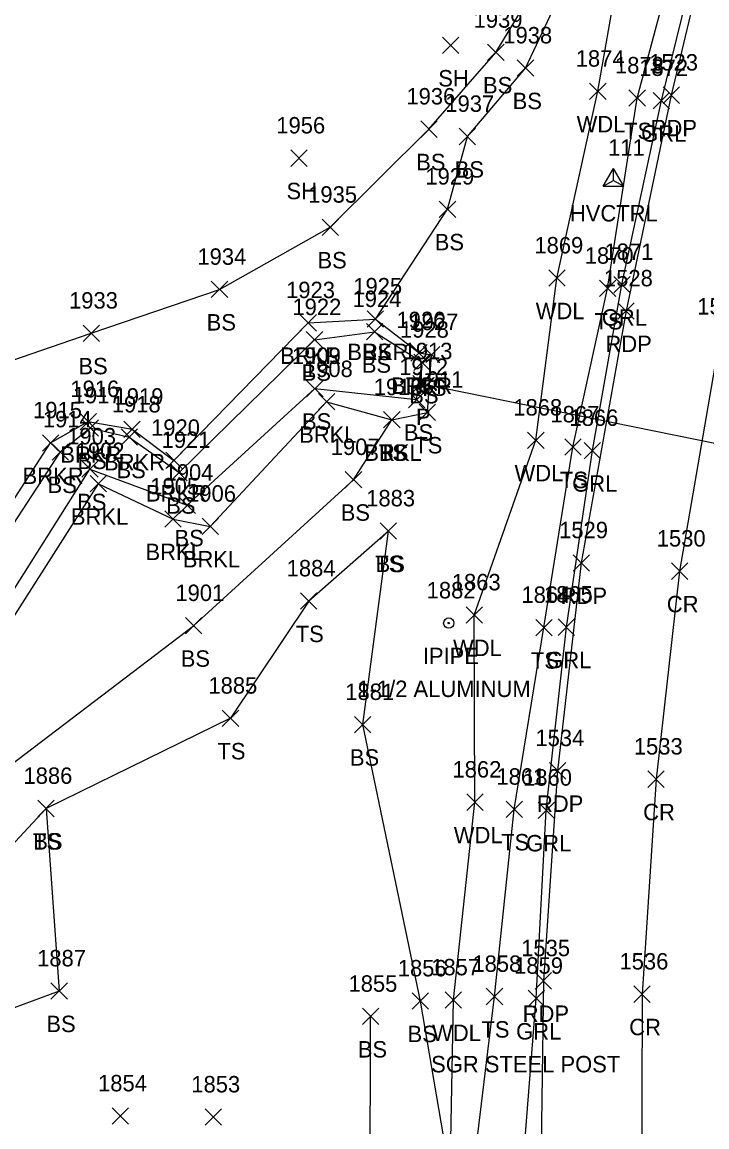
# Model space of a CAD drawing. Extents: x 1885914 to 1887218, y 756253 to 760620.
# Drawn here: x 1886356.8 to 1886440.2, y 759652.9 to 759787.4 of the extents above; entities that cross this region are included whole.
import ezdxf

# ---------------------------------------------------------------- set-up
doc = ezdxf.new("R2010")
doc.units = 0
for name, color, linetype in [('C_A', 7, 'Continuous'), ('C_I', 7, 'Continuous'), ('CPSM', 7, 'Continuous'), ('D_A', 7, 'Continuous'), ('D_I', 7, 'Continuous'), ('D_TIC', 7, 'Continuous'), ('DCP', 7, 'Continuous'), ('L_A', 7, 'Continuous'), ('L_I', 7, 'Continuous'), ('L_TIC', 7, 'Continuous'), ('LAWA', 7, 'Continuous'), ('LAWE', 7, 'Continuous'), ('LELB', 7, 'Continuous'), ('M_A', 7, 'Continuous'), ('M_C', 7, 'Continuous'), ('M_I', 7, 'Continuous'), ('MPIP', 7, 'Continuous'), ('P_A', 7, 'Continuous'), ('P_I', 7, 'Continuous'), ('P_TIC', 7, 'Continuous'), ('PET', 7, 'Continuous'), ('PRC', 7, 'Continuous'), ('R_A', 7, 'Continuous'), ('R_C', 7, 'Continuous'), ('R_I', 7, 'Continuous'), ('R_TIC', 7, 'Continuous'), ('RGR', 7, 'Continuous')]:
    doc.layers.add(name, color=color, linetype=linetype)

msp = doc.modelspace()

# ---------------------------------------------------------------- linework, layer by layer
at = {"layer": 'CPSM'}
for p, q in [((1886427.59, 759767.4), (1886428.84, 759769.57)), ((1886430.09, 759767.4), (1886428.84, 759769.57)), ((1886428.84, 759768.12), (1886428.84, 759769.57)), ((1886427.59, 759767.4), (1886428.84, 759768.12)), ((1886428.84, 759768.12), (1886428.84, 759768.12)), ((1886428.84, 759768.12), (1886430.09, 759767.4)), ((1886427.59, 759767.4), (1886430.09, 759767.4))]:
    msp.add_line(p, q, dxfattribs=at)
at = {"layer": 'D_TIC'}
for points in [[(1886404.41, 759742.36), (1886406.41, 759744.36)], [(1886406.41, 759742.36), (1886404.41, 759744.36)]]:
    msp.add_lwpolyline(points, dxfattribs=at)
at = {"layer": 'DCP'}
msp.add_lwpolyline([(1886482.74, 759727.67), (1886405.41, 759743.36)], dxfattribs=at)
at = {"layer": 'L_TIC'}
for points in [[(1886408.01, 759783.55), (1886410.01, 759785.55)], [(1886410.01, 759783.55), (1886408.01, 759785.55)], [(1886413.51, 759782.7), (1886415.51, 759784.7)], [(1886415.51, 759782.7), (1886413.51, 759784.7)], [(1886417.12, 759780.79), (1886419.12, 759782.79)], [(1886419.12, 759780.79), (1886417.12, 759782.79)], [(1886425.93, 759777.96), (1886427.93, 759779.96)], [(1886427.93, 759777.96), (1886425.93, 759779.96)], [(1886430.72, 759777.14), (1886432.72, 759779.14)], [(1886432.72, 759777.14), (1886430.72, 759779.14)], [(1886405.37, 759773.36), (1886407.37, 759775.36)], [(1886407.37, 759773.36), (1886405.37, 759775.36)], [(1886410.05, 759772.46), (1886412.05, 759774.46)], [(1886412.05, 759772.46), (1886410.05, 759774.46)], [(1886389.53, 759769.83), (1886391.53, 759771.83)], [(1886391.53, 759769.83), (1886389.53, 759771.83)], [(1886407.63, 759763.61), (1886409.63, 759765.61)], [(1886409.63, 759763.61), (1886407.63, 759765.61)], [(1886393.35, 759761.41), (1886395.35, 759763.41)], [(1886395.35, 759761.41), (1886393.35, 759763.41)], [(1886420.95, 759755.23), (1886422.95, 759757.23)], [(1886422.95, 759755.23), (1886420.95, 759757.23)], [(1886379.86, 759753.85), (1886381.86, 759755.85)], [(1886381.86, 759753.85), (1886379.86, 759755.85)], [(1886427.12, 759753.98), (1886429.12, 759755.98)], [(1886429.12, 759753.98), (1886427.12, 759755.98)], [(1886390.66, 759749.79), (1886392.66, 759751.79)], [(1886392.66, 759749.79), (1886390.66, 759751.79)], [(1886398.84, 759750.25), (1886400.84, 759752.25)], [(1886400.84, 759750.25), (1886398.84, 759752.25)], [(1886398.84, 759750.25), (1886400.84, 759752.25)], [(1886400.84, 759750.25), (1886398.84, 759752.25)], [(1886364.24, 759748.52), (1886366.24, 759750.52)], [(1886366.24, 759748.52), (1886364.24, 759750.52)], [(1886398.75, 759748.71), (1886400.75, 759750.71)], [(1886400.75, 759748.71), (1886398.75, 759750.71)], [(1886391.43, 759747.73), (1886393.43, 759749.73)], [(1886393.43, 759747.73), (1886391.43, 759749.73)], [(1886404.16, 759746.14), (1886406.16, 759748.14)], [(1886406.16, 759746.14), (1886404.16, 759748.14)], [(1886404.16, 759746.14), (1886406.16, 759748.14)], [(1886406.16, 759746.14), (1886404.16, 759748.14)], [(1886405.68, 759745.9), (1886407.68, 759747.9)], [(1886407.68, 759745.9), (1886405.68, 759747.9)], [(1886405.68, 759745.9), (1886407.68, 759747.9)], [(1886407.68, 759745.9), (1886405.68, 759747.9)], [(1886404.53, 759744.98), (1886406.53, 759746.98)], [(1886406.53, 759744.98), (1886404.53, 759746.98)], [(1886404.53, 759744.98), (1886406.53, 759746.98)], [(1886406.53, 759744.98), (1886404.53, 759746.98)], [(1886391.47, 759741.78), (1886393.47, 759743.78)], [(1886393.47, 759741.78), (1886391.47, 759743.78)], [(1886392.91, 759740.19), (1886394.91, 759742.19)], [(1886394.91, 759740.19), (1886392.91, 759742.19)], [(1886403.87, 759740.44), (1886405.87, 759742.44)], [(1886405.87, 759740.44), (1886403.87, 759742.44)], [(1886405.17, 759738.89), (1886407.17, 759740.89)], [(1886407.17, 759738.89), (1886405.17, 759740.89)], [(1886363.88, 759737.76), (1886365.88, 759739.76)], [(1886365.88, 759737.76), (1886363.88, 759739.76)], [(1886400.85, 759737.99), (1886402.85, 759739.99)], [(1886402.85, 759737.99), (1886400.85, 759739.99)], [(1886400.85, 759737.99), (1886402.85, 759739.99)], [(1886402.85, 759737.99), (1886400.85, 759739.99)], [(1886400.85, 759737.99), (1886402.85, 759739.99)], [(1886402.85, 759737.99), (1886400.85, 759739.99)], [(1886364.13, 759736.99), (1886366.13, 759738.99)], [(1886366.13, 759736.99), (1886364.13, 759738.99)], [(1886369.21, 759736.83), (1886371.21, 759738.83)], [(1886371.21, 759736.83), (1886369.21, 759738.83)], [(1886359.29, 759735.17), (1886361.29, 759737.17)], [(1886361.29, 759735.17), (1886359.29, 759737.17)], [(1886368.88, 759735.88), (1886370.88, 759737.88)], [(1886370.88, 759735.88), (1886368.88, 759737.88)], [(1886418.38, 759735.5), (1886420.38, 759737.5)], [(1886420.38, 759735.5), (1886418.38, 759737.5)], [(1886360.48, 759734.07), (1886362.48, 759736.07)], [(1886362.48, 759734.07), (1886360.48, 759736.07)], [(1886422.9, 759734.67), (1886424.9, 759736.67)], [(1886424.9, 759734.67), (1886422.9, 759736.67)], [(1886374.31, 759733.04), (1886376.31, 759735.04)], [(1886376.31, 759733.04), (1886374.31, 759735.04)], [(1886364.08, 759731.99), (1886366.08, 759733.99)], [(1886366.08, 759731.99), (1886364.08, 759733.99)], [(1886374.93, 759731.56), (1886376.93, 759733.56)], [(1886376.93, 759731.56), (1886374.93, 759733.56)], [(1886365.11, 759730.21), (1886367.11, 759732.21)], [(1886367.11, 759730.21), (1886365.11, 759732.21)], [(1886396.18, 759730.7), (1886398.18, 759732.7)], [(1886398.18, 759730.7), (1886396.18, 759732.7)], [(1886375.94, 759727.59), (1886377.94, 759729.59)], [(1886377.94, 759727.59), (1886375.94, 759729.59)], [(1886374.2, 759725.91), (1886376.2, 759727.91)], [(1886376.2, 759725.91), (1886374.2, 759727.91)], [(1886378.74, 759725.02), (1886380.74, 759727.02)], [(1886380.74, 759725.02), (1886378.74, 759727.02)], [(1886400.43, 759724.45), (1886402.43, 759726.45)], [(1886402.43, 759724.45), (1886400.43, 759726.45)], [(1886400.43, 759724.45), (1886402.43, 759726.45)], [(1886402.43, 759724.45), (1886400.43, 759726.45)], [(1886390.73, 759715.93), (1886392.73, 759717.93)], [(1886392.73, 759715.93), (1886390.73, 759717.93)], [(1886410.89, 759714.23), (1886412.89, 759716.23)], [(1886412.89, 759714.23), (1886410.89, 759716.23)], [(1886376.7, 759712.93), (1886378.7, 759714.93)], [(1886378.7, 759712.93), (1886376.7, 759714.93)], [(1886419.37, 759712.7), (1886421.37, 759714.7)], [(1886421.37, 759712.7), (1886419.37, 759714.7)], [(1886381.2, 759701.66), (1886383.2, 759703.66)], [(1886383.2, 759701.66), (1886381.2, 759703.66)], [(1886397.3, 759700.89), (1886399.3, 759702.89)], [(1886399.3, 759700.89), (1886397.3, 759702.89)], [(1886358.74, 759690.68), (1886360.74, 759692.68)], [(1886360.74, 759690.68), (1886358.74, 759692.68)], [(1886358.74, 759690.68), (1886360.74, 759692.68)], [(1886360.74, 759690.68), (1886358.74, 759692.68)], [(1886410.97, 759691.45), (1886412.97, 759693.45)], [(1886412.97, 759691.45), (1886410.97, 759693.45)], [(1886415.75, 759690.58), (1886417.75, 759692.58)], [(1886417.75, 759690.58), (1886415.75, 759692.58)], [(1886360.34, 759668.47), (1886362.34, 759670.47)], [(1886362.34, 759668.47), (1886360.34, 759670.47)], [(1886413.35, 759667.8), (1886415.35, 759669.8)], [(1886415.35, 759667.8), (1886413.35, 759669.8)], [(1886404.32, 759667.25), (1886406.32, 759669.25)], [(1886406.32, 759667.25), (1886404.32, 759669.25)], [(1886408.34, 759667.38), (1886410.34, 759669.38)], [(1886410.34, 759667.38), (1886408.34, 759669.38)], [(1886398.26, 759665.38), (1886400.26, 759667.38)], [(1886400.26, 759665.38), (1886398.26, 759667.38)], [(1886367.77, 759653.26), (1886369.77, 759655.26)], [(1886369.77, 759653.26), (1886367.77, 759655.26)], [(1886379.12, 759653.13), (1886381.12, 759655.13)], [(1886381.12, 759653.13), (1886379.12, 759655.13)]]:
    msp.add_lwpolyline(points, dxfattribs=at)
at = {"layer": 'LAWA'}
msp.add_lwpolyline([(1886420.25, 759558.57), (1886411.95, 759586.16), (1886411.02, 759591.73), (1886408.64, 759606.82), (1886405.28, 759619.96), (1886408.97, 759647.11), (1886409.34, 759668.38), (1886411.97, 759692.45), (1886411.89, 759715.23), (1886419.38, 759736.5), (1886421.95, 759756.23), (1886426.93, 759778.96), (1886430, 759796.54), (1886430.97, 759806.71), (1886430.75, 759808.98), (1886434.23, 759819.8), (1886435.82, 759833.71), (1886420.59, 759830.9), (1886400.43, 759842), (1886371.48, 759869.99)], dxfattribs=at)
at = {"layer": 'LAWE'}
for points in [[(1886317, 759683.03), (1886341.18, 759706.68), (1886360.29, 759736.17), (1886364.88, 759738.76), (1886370.21, 759737.83), (1886375.31, 759734.04), (1886391.66, 759750.79), (1886399.84, 759751.25), (1886405.16, 759747.14)], [(1886319.97, 759675.42), (1886346.73, 759700.79), (1886366.11, 759731.21), (1886375.2, 759726.91), (1886379.74, 759726.02), (1886393.91, 759741.19), (1886401.85, 759738.99)]]:
    msp.add_lwpolyline(points, dxfattribs=at)
at = {"layer": 'LELB'}
for points in [[(1886482.43, 759330.53), (1886473.8, 759362.16), (1886466.41, 759391.35), (1886456.38, 759428.48), (1886448.84, 759459.02), (1886441.76, 759486.12), (1886435.76, 759515.56), (1886431.42, 759535.05), (1886426.06, 759559.46), (1886421.11, 759588.4), (1886418.79, 759606.26), (1886412.24, 759623.91), (1886411.78, 759647.7), (1886414.35, 759668.8), (1886416.75, 759691.58), (1886420.37, 759713.7), (1886423.9, 759735.67), (1886428.12, 759754.98), (1886431.72, 759778.14), (1886436.25, 759795.18), (1886439.73, 759830.38)], [(1886307, 759709.14), (1886318.52, 759725.02), (1886338.68, 759740.39), (1886365.24, 759749.52), (1886380.86, 759754.85), (1886394.35, 759762.41), (1886406.37, 759774.36), (1886414.51, 759783.7), (1886422.61, 759797.12), (1886430.75, 759808.98)], [(1886399.84, 759751.25), (1886408.63, 759764.61), (1886411.05, 759773.46), (1886418.12, 759781.79), (1886424.84, 759796), (1886430.97, 759806.71)], [(1886317.21, 759681.25), (1886341.81, 759704.94), (1886361.48, 759735.07), (1886365.13, 759737.99), (1886369.88, 759736.88), (1886375.93, 759732.56), (1886392.43, 759748.73), (1886399.75, 759749.71), (1886405.53, 759745.98)], [(1886401.85, 759738.99), (1886406.17, 759739.89), (1886406.68, 759746.9)], [(1886405.16, 759747.14), (1886406.68, 759746.9)], [(1886319.13, 759676.73), (1886345.61, 759702.22), (1886365.08, 759732.99), (1886376.94, 759728.59), (1886392.47, 759742.78), (1886404.87, 759741.44), (1886405.53, 759745.98)], [(1886304.72, 759654.88), (1886325.87, 759667.69), (1886353.55, 759695.57), (1886377.7, 759713.93), (1886397.18, 759731.7), (1886401.85, 759738.99)], [(1886401.43, 759725.45), (1886391.73, 759716.93), (1886382.2, 759702.66), (1886359.74, 759691.68), (1886327.3, 759656.86)], [(1886479.66, 759329.52), (1886471.03, 759361.21), (1886461.96, 759390.83), (1886454.24, 759427.83), (1886447.27, 759458.84), (1886440.35, 759485.71), (1886434.88, 759515.3), (1886430.89, 759534.99), (1886424.93, 759559.47), (1886417.7, 759587.99), (1886415.39, 759606.58), (1886409.44, 759622.11), (1886408.97, 759647.11), (1886405.32, 759668.25), (1886398.3, 759701.89), (1886401.43, 759725.45)], [(1886359.74, 759691.68), (1886361.34, 759669.47), (1886327.3, 759656.86)], [(1886476.45, 759328.91), (1886467.85, 759360.49), (1886459.66, 759390.14), (1886451.87, 759427.06), (1886445.59, 759458.5), (1886438.66, 759485.01), (1886433.8, 759515.01), (1886429.52, 759534.9), (1886422.3, 759559.11), (1886414.83, 759587.35), (1886411.02, 759591.73), (1886403.8, 759605.65), (1886400.43, 759619.74), (1886399.2, 759644.65), (1886399.26, 759666.38)]]:
    msp.add_lwpolyline(points, dxfattribs=at)
at = {"layer": 'MPIP'}
for radius in [0.625, 0.0833]:
    msp.add_circle((1886408.78, 759714.25), radius, dxfattribs=at)
at = {"layer": 'P_TIC'}
for points in [[(1886434.87, 759777.49), (1886436.87, 759779.49)], [(1886436.87, 759777.49), (1886434.87, 759779.49)], [(1886429.37, 759751.23), (1886431.37, 759753.23)], [(1886431.37, 759751.23), (1886429.37, 759753.23)], [(1886423.92, 759720.57), (1886425.92, 759722.57)], [(1886425.92, 759720.57), (1886423.92, 759722.57)], [(1886435.89, 759719.56), (1886437.89, 759721.56)], [(1886437.89, 759719.56), (1886435.89, 759721.56)], [(1886421.03, 759695.27), (1886423.03, 759697.27)], [(1886423.03, 759695.27), (1886421.03, 759697.27)], [(1886433.02, 759694.25), (1886435.02, 759696.25)], [(1886435.02, 759694.25), (1886433.02, 759696.25)], [(1886419.3, 759669.71), (1886421.3, 759671.71)], [(1886421.3, 759669.71), (1886419.3, 759671.71)], [(1886431.32, 759668.09), (1886433.32, 759670.09)], [(1886433.32, 759668.09), (1886431.32, 759670.09)]]:
    msp.add_lwpolyline(points, dxfattribs=at)
at = {"layer": 'PET'}
msp.add_lwpolyline([(1886505.21, 759975.04), (1886485.32, 759931.76), (1886475.82, 759908.45), (1886466.13, 759882.96), (1886456.93, 759855.61), (1886449.99, 759833.06), (1886442.98, 759808.26), (1886435.87, 759778.49), (1886430.37, 759752.23), (1886424.92, 759721.57), (1886422.03, 759696.27), (1886420.3, 759670.71), (1886419.91, 759641.82), (1886421.23, 759616.47), (1886424.6, 759585.72), (1886430.09, 759554.32), (1886435.19, 759528.63), (1886443.72, 759490.84), (1886451.63, 759459.71), (1886459.13, 759429.12), (1886468.69, 759393.26), (1886479.71, 759351.07), (1886485.06, 759331.17)], dxfattribs=at)
at = {"layer": 'PRC'}
msp.add_lwpolyline([(1886516.05, 759969.43), (1886496.99, 759926.69), (1886487.66, 759904.2), (1886477.68, 759877.96), (1886468.59, 759851.92), (1886461.77, 759829.93), (1886454.6, 759805.62), (1886447.16, 759775.82), (1886441.74, 759748.8), (1886436.89, 759720.56), (1886434.02, 759695.25), (1886432.32, 759669.09), (1886432.26, 759642.82), (1886433.77, 759616.6), (1886436.98, 759587.84), (1886441.74, 759556.93), (1886446.53, 759531.43), (1886454.86, 759493.34), (1886462.57, 759461.76), (1886470.69, 759431.8), (1886480.02, 759395.82), (1886491.53, 759354.96), (1886496.99, 759335.08)], dxfattribs=at)
at = {"layer": 'R_TIC'}
for points in [[(1886433.67, 759776.83), (1886435.67, 759778.83)], [(1886435.67, 759776.83), (1886433.67, 759778.83)], [(1886428.87, 759754.44), (1886430.87, 759756.44)], [(1886430.87, 759754.44), (1886428.87, 759756.44)], [(1886425.27, 759734.24), (1886427.27, 759736.24)], [(1886427.27, 759734.24), (1886425.27, 759736.24)], [(1886422.11, 759712.75), (1886424.11, 759714.75)], [(1886424.11, 759712.75), (1886422.11, 759714.75)], [(1886419.66, 759690.46), (1886421.66, 759692.46)], [(1886421.66, 759690.46), (1886419.66, 759692.46)], [(1886418.44, 759667.57), (1886420.44, 759669.57)], [(1886420.44, 759667.57), (1886418.44, 759669.57)]]:
    msp.add_lwpolyline(points, dxfattribs=at)
at = {"layer": 'RGR'}
msp.add_lwpolyline([(1886414.69, 759633.21), (1886417.71, 759646.92), (1886419.44, 759668.57), (1886420.66, 759691.46), (1886423.11, 759713.75), (1886426.27, 759735.24), (1886429.87, 759755.44), (1886434.67, 759777.83), (1886438.97, 759795.37), (1886443.17, 759815.48), (1886444.3, 759833.77)], dxfattribs=at)

# ---------------------------------------------------------------- texts
at = {"layer": 'C_A'}
msp.add_text('HVCTRL', height=2, dxfattribs=at).set_placement((1886423.53, 759763.12))
at = {"layer": 'C_I'}
msp.add_text('111', height=2, dxfattribs=at).set_placement((1886428.18, 759771.12))
at = {"layer": 'D_A'}
msp.add_text('P', height=2, dxfattribs=at).set_placement((1886404.79, 759738.36))
at = {"layer": 'D_I'}
msp.add_text('1913', height=2, dxfattribs=at).set_placement((1886403.28, 759746.36))
at = {"layer": 'L_A'}
for s, p in [('SH', (1886407.5, 759779.55)), ('BS', (1886412.95, 759778.7)), ('BS', (1886416.56, 759776.79)), ('WDL', (1886424.35, 759773.96)), ('TS', (1886430.13, 759773.14)), ('BS', (1886404.81, 759769.36)), ('BS', (1886409.5, 759768.46)), ('SH', (1886389.02, 759765.83)), ('BS', (1886407.07, 759759.61)), ('BS', (1886392.79, 759757.41)), ('WDL', (1886419.37, 759751.23)), ('BS', (1886379.3, 759749.85)), ('TS', (1886426.53, 759749.98)), ('BRKR', (1886388.25, 759745.79)), ('BRKR', (1886396.43, 759746.25)), ('BS', (1886398.28, 759746.25)), ('BS', (1886363.68, 759744.52)), ('BS', (1886398.19, 759744.71)), ('BS', (1886390.87, 759743.73)), ('BRKR', (1886401.75, 759742.14)), ('TS', (1886403.57, 759742.14)), ('TS', (1886405.09, 759741.9)), ('TS', (1886405.09, 759741.9)), ('BS', (1886403.97, 759740.98)), ('BS', (1886403.97, 759740.98)), ('BS', (1886390.91, 759737.78)), ('BRKL', (1886390.56, 759736.19)), ('BS', (1886403.31, 759736.44)), ('TS', (1886404.58, 759734.89)), ('BRKR', (1886361.48, 759733.76)), ('BRKL', (1886398.5, 759733.99)), ('TS', (1886400.26, 759733.99)), ('BS', (1886400.29, 759733.99)), ('BS', (1886363.57, 759732.99)), ('BRKR', (1886366.8, 759732.83)), ('BRKR', (1886356.88, 759731.17)), ('BS', (1886368.32, 759731.88)), ('WDL', (1886416.79, 759731.5)), ('BS', (1886359.92, 759730.07)), ('TS', (1886422.31, 759730.67)), ('BS', (1886363.52, 759727.99)), ('BRKR', (1886371.9, 759729.04)), ('BS', (1886374.37, 759727.56)), ('BS', (1886395.62, 759726.7)), ('BRKL', (1886362.76, 759726.21)), ('BS', (1886375.38, 759723.59)), ('BRKL', (1886371.85, 759721.91)), ('BRKL', (1886376.39, 759721.02)), ('TS', (1886399.83, 759720.45)), ('BS', (1886399.87, 759720.45)), ('TS', (1886390.14, 759711.93)), ('WDL', (1886409.3, 759710.23)), ('BS', (1886376.14, 759708.93)), ('TS', (1886418.78, 759708.7)), ('TS', (1886380.61, 759697.66)), ('BS', (1886396.74, 759696.89)), ('TS', (1886358.15, 759686.68)), ('BS', (1886358.18, 759686.68)), ('WDL', (1886409.39, 759687.45)), ('TS', (1886415.16, 759686.58)), ('BS', (1886359.78, 759664.47)), ('TS', (1886412.76, 759663.8)), ('BS', (1886403.76, 759663.25)), ('WDL', (1886406.75, 759663.38)), ('BS', (1886397.7, 759661.38))]:
    msp.add_text(s, height=2, dxfattribs=at).set_placement(p)
at = {"layer": 'L_I'}
for s, p in [('1939', (1886411.81, 759786.7)), ('1938', (1886415.42, 759784.79)), ('1874', (1886424.24, 759781.96)), ('1873', (1886429.02, 759781.14)), ('1936', (1886403.62, 759777.36)), ('1937', (1886408.36, 759776.46)), ('1956', (1886387.78, 759773.83)), ('1929', (1886405.93, 759767.61)), ('1935', (1886391.66, 759765.41)), ('1869', (1886419.21, 759759.23)), ('1934', (1886378.17, 759757.85)), ('1870', (1886425.34, 759757.98)), ('1923', (1886388.97, 759753.79)), ('1925', (1886397.15, 759754.25)), ('1925', (1886397.15, 759754.25)), ('1933', (1886362.54, 759752.52)), ('1924', (1886397.06, 759752.71)), ('1922', (1886389.74, 759751.73)), ('1926', (1886402.41, 759750.14)), ('1926', (1886402.41, 759750.14)), ('1927', (1886403.99, 759749.9)), ('1927', (1886403.99, 759749.9)), ('1928', (1886402.84, 759748.98)), ('1928', (1886402.84, 759748.98)), ('1909', (1886389.69, 759745.78)), ('1908', (1886391.14, 759744.19)), ('1912', (1886402.74, 759744.44)), ('1911', (1886404.61, 759742.89)), ('1916', (1886362.7, 759741.76)), ('1910', (1886399.64, 759741.99)), ('1910', (1886399.64, 759741.99)), ('1910', (1886399.64, 759741.99)), ('1917', (1886363, 759740.99)), ('1919', (1886368.08, 759740.83)), ('1915', (1886358.16, 759739.17)), ('1918', (1886367.75, 759739.88)), ('1868', (1886416.64, 759739.5)), ('1914', (1886359.35, 759738.07)), ('1867', (1886421.16, 759738.67)), ('1920', (1886372.53, 759737.04)), ('1903', (1886362.31, 759735.99)), ('1921', (1886373.81, 759735.56)), ('1902', (1886363.34, 759734.21)), ('1907', (1886394.41, 759734.7)), ('1904', (1886374.17, 759731.59)), ('1905', (1886372.43, 759729.91)), ('1906', (1886376.92, 759729.02)), ('1883', (1886398.73, 759728.45)), ('1883', (1886398.73, 759728.45)), ('1884', (1886389.04, 759719.93)), ('1863', (1886409.15, 759718.23)), ('1901', (1886375.49, 759716.93)), ('1864', (1886417.63, 759716.7)), ('1885', (1886379.51, 759705.66)), ('1881', (1886396.18, 759704.89)), ('1886', (1886356.99, 759694.68)), ('1886', (1886356.99, 759694.68)), ('1862', (1886409.23, 759695.45)), ('1861', (1886414.58, 759694.58)), ('1887', (1886358.65, 759672.47)), ('1858', (1886411.66, 759671.8)), ('1856', (1886402.57, 759671.25)), ('1857', (1886406.64, 759671.38)), ('1855', (1886396.57, 759669.38)), ('1854', (1886366.07, 759657.26)), ('1853', (1886377.43, 759657.13))]:
    msp.add_text(s, height=2, dxfattribs=at).set_placement(p)
at = {"layer": 'M_A'}
msp.add_text('IPIPE', height=2, dxfattribs=at).set_placement((1886405.62, 759709.25))
at = {"layer": 'M_C'}
msp.add_text('1-1/2 ALUMINUM', height=2, dxfattribs=at).set_placement((1886397.65, 759705.25))
at = {"layer": 'M_I'}
msp.add_text('1882', height=2, dxfattribs=at).set_placement((1886406.09, 759717.25))
at = {"layer": 'P_A'}
for s, p in [('RDP', (1886433.36, 759773.49)), ('RDP', (1886427.86, 759747.23)), ('RDP', (1886422.41, 759716.57)), ('CR', (1886435.33, 759715.56)), ('RDP', (1886419.52, 759691.27)), ('CR', (1886432.45, 759690.25)), ('RDP', (1886417.78, 759665.71)), ('CR', (1886430.75, 759664.09))]:
    msp.add_text(s, height=2, dxfattribs=at).set_placement(p)
at = {"layer": 'P_I'}
for s, p in [('1523', (1886433.18, 759781.49)), ('1528', (1886427.68, 759755.23)), ('1527', (1886439.04, 759751.8)), ('1529', (1886422.22, 759724.57)), ('1530', (1886434.11, 759723.56)), ('1534', (1886419.33, 759699.27)), ('1533', (1886431.32, 759698.25)), ('1535', (1886417.6, 759673.71)), ('1536', (1886429.57, 759672.09))]:
    msp.add_text(s, height=2, dxfattribs=at).set_placement(p)
at = {"layer": 'R_A'}
for p in [(1886432.21, 759772.83), (1886427.41, 759750.44), (1886423.81, 759730.24), (1886420.65, 759708.75), (1886418.2, 759686.46), (1886416.98, 759663.57)]:
    msp.add_text('GRL', height=2, dxfattribs=at).set_placement(p)
at = {"layer": 'R_C'}
msp.add_text('SGR STEEL POST', height=2, dxfattribs=at).set_placement((1886406.63, 759659.57))
at = {"layer": 'R_I'}
for s, p in [('1872', (1886431.97, 759780.83)), ('1871', (1886427.74, 759758.44)), ('1866', (1886423.48, 759738.24)), ('1865', (1886420.37, 759716.75)), ('1860', (1886417.83, 759694.46)), ('1859', (1886416.74, 759671.57))]:
    msp.add_text(s, height=2, dxfattribs=at).set_placement(p)

doc.saveas('drawing.dxf')
